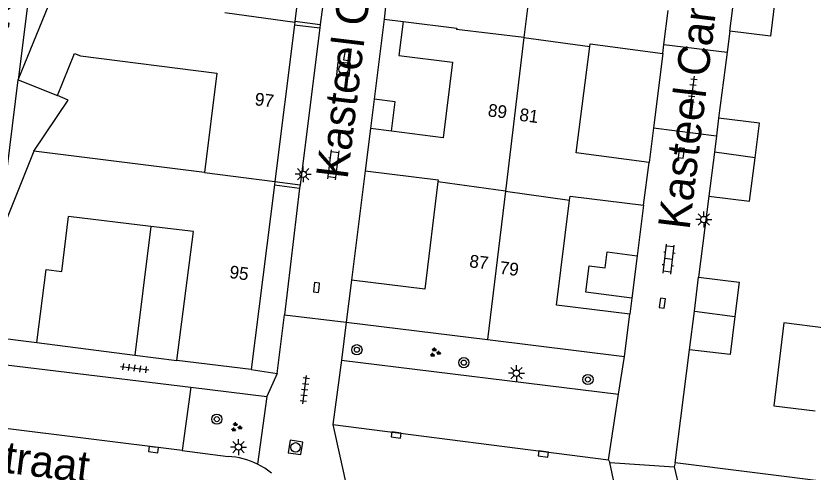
# Model space of a CAD drawing. Extents: x 131000 to 133014, y 396499 to 399001.
# Drawn here: x 131705.9 to 131768.4, y 396712.4 to 396748.2 of the extents above; entities that cross this region are included whole.
import ezdxf

# ---------------------------------------------------------------- set-up
doc = ezdxf.new("R2010")
doc.units = 0
for name, color, linetype in [('gg-afsc-erfafscheiding', 7, 'Continuous'), ('gg-afsc-muur', 7, 'Continuous'), ('gg-anno-huisnummerreeks BGT', 7, 'Continuous'), ('gg-anno-openbare ruimte label', 7, 'Continuous'), ('gg-bbg-bijgebouw', 7, 'Continuous'), ('gg-bbg-gedigitaliseerde bebouwing', 7, 'Continuous'), ('gg-bbg-gedigitaliseerde bijgebouw', 7, 'Continuous'), ('gg-bbg-hoofdgebouw', 7, 'Continuous'), ('gg-bbg-luifel en loopbrug', 7, 'Continuous'), ('gg-bbg-tussenscheiding', 7, 'Continuous'), ('gg-knt-verharding', 7, 'Continuous'), ('gg-knt-verharding nz', 7, 'Continuous'), ('gt-grn-vlakafsluiter', 7, 'Continuous'), ('gt-grn-weggrens', 7, 'Continuous'), ('gt-symb-boom', 7, 'Continuous'), ('gt-symb-groenvak', 7, 'Continuous'), ('gt-symb-klinker verharding', 7, 'Continuous'), ('gt-symb-kolk', 7, 'Continuous'), ('gt-symb-lichtmast', 7, 'Continuous'), ('gt-symb-rioolschacht', 7, 'Continuous'), ('gt-symb-tegel verharding', 7, 'Continuous')]:
    doc.layers.add(name, color=color, linetype=linetype)

# ---------------------------------------------------------------- blocks, each defined once
blk = doc.blocks.new('gt0-BOOM')
at = {"layer": 'gt-symb-boom'}
for radius in [0.4, 0.2]:
    blk.add_circle((0, 0), radius, dxfattribs=at)
blk = doc.blocks.new('gt0-KOLK')
at = {"layer": 'gt-symb-kolk'}
blk.add_lwpolyline([(0, 0), (0.375, 0), (0.375, 0.4), (-0.375, 0.4), (-0.375, 0), (0, 0)], dxfattribs=at)
blk = doc.blocks.new('gt0-LMAST')
at = {"layer": 'gt-symb-lichtmast'}
for p, q in [((-0.182, 0.173), (-0.447, 0.438)), ((-0.005, 0.246), (-0.005, 0.621)), ((0.172, 0.173), (0.437, 0.438)), ((-0.255, -0.004), (-0.63, -0.004)), ((-0.182, -0.181), (-0.447, -0.446)), ((-0.005, -0.254), (-0.005, -0.629)), ((0.437, -0.446), (0.172, -0.181)), ((0.245, -0.004), (0.62, -0.004))]:
    blk.add_line(p, q, dxfattribs=at)
blk.add_circle((-0.005, -0.004), 0.25, dxfattribs=at)
blk = doc.blocks.new('gt0-GRVAK')
at = {"layer": 'gt-symb-groenvak'}
for p, q in [((-0.11, 0.189), (-0.228, 0.24)), ((-0.182, 0.153), (0.088, 0.153)), ((-0.091, 0.211), (-0.156, 0.322)), ((-0.047, 0.214), (-0.047, 0.393)), ((-0.004, 0.211), (0.061, 0.322)), ((0.015, 0.189), (0.133, 0.24)), ((0.262, -0.052), (0.197, 0.059)), ((0.305, -0.049), (0.305, 0.13)), ((0.349, -0.052), (0.414, 0.059)), ((-0.245, -0.228), (-0.363, -0.177)), ((-0.318, -0.264), (-0.047, -0.264)), ((-0.226, -0.206), (-0.291, -0.095)), ((-0.183, -0.203), (-0.183, -0.024)), ((-0.139, -0.206), (-0.074, -0.095)), ((-0.12, -0.228), (-0.002, -0.177)), ((0.243, -0.074), (0.125, -0.023)), ((0.17, -0.11), (0.441, -0.11)), ((0.368, -0.074), (0.486, -0.023))]:
    blk.add_line(p, q, dxfattribs=at)
blk = doc.blocks.new('gt0-RS')
at = {"layer": 'gt-symb-rioolschacht'}
blk.add_lwpolyline([(-0.5, -0.5), (0.5, -0.5), (0.5, 0.5), (-0.5, 0.5)], close=True, dxfattribs=at)
blk.add_circle((0, 0), 0.375, dxfattribs=at)
blk = doc.blocks.new('gt0-TEG1')
at = {"layer": 'gt-symb-tegel verharding'}
for p, q in [((-1.125, 0), (1.125, 0)), ((-0.9, -0.25), (-0.9, 0.25)), ((-0.45, -0.25), (-0.45, 0.25)), ((0, -0.25), (0, 0.25)), ((0.45, -0.25), (0.45, 0.25)), ((0.9, -0.25), (0.9, 0.25))]:
    blk.add_line(p, q, dxfattribs=at)
blk = doc.blocks.new('gt0-KL1')
at = {"layer": 'gt-symb-klinker verharding'}
for p, q in [((-1.15, 0.3), (1.15, 0.3)), ((-1, -0.3), (-1, 0.3)), ((-0.5, 0.3), (-0.5, 0.45)), ((0, -0.3), (0, 0.3)), ((0.5, 0.3), (0.5, 0.45)), ((1, -0.3), (1, 0.3)), ((-1.15, -0.3), (1.15, -0.3)), ((-0.5, -0.45), (-0.5, -0.3)), ((0.5, -0.45), (0.5, -0.3))]:
    blk.add_line(p, q, dxfattribs=at)

msp = doc.modelspace()

# ---------------------------------------------------------------- linework, layer by layer
at = {"layer": 'gg-afsc-erfafscheiding'}
for p, q in [((131734.78, 396747.94), (131733.999, 396741.681)), ((131761.9, 396747.01), (131761.688, 396745.348)), ((131756.65, 396745.26), (131755.913, 396739.423)), ((131761.688, 396745.348), (131761.537, 396744.163)), ((131755.913, 396739.423), (131755.57, 396736.7)), ((131755.13, 396733.36), (131754.629, 396729.381)), ((131754.21, 396726.062), (131754.05, 396724.79)), ((131757.62, 396713.13), (131758.74, 396722)), ((131779.39, 396710.379), (131757.62, 396713.13))]:
    msp.add_line(p, q, dxfattribs=at)
at = {"layer": 'gg-afsc-muur'}
for p, q in [((131727.792, 396747.788), (131729.778, 396747.541)), ((131727.757, 396747.51), (131729.743, 396747.263)), ((131729.778, 396747.541), (131729.743, 396747.263)), ((131761.537, 396744.163), (131761.03, 396740.19)), ((131733.3, 396736.05), (131732.22, 396727.47)), ((131726.207, 396735.197), (131728.192, 396734.95)), ((131726.175, 396734.94), (131728.16, 396734.693)), ((131728.192, 396734.95), (131728.16, 396734.693)), ((131760.26, 396734.06), (131759.46, 396727.7)), ((131707.546, 396722.579), (131715.228, 396721.58))]:
    msp.add_line(p, q, dxfattribs=at)
at = {"layer": 'gg-bbg-bijgebouw'}
for p, q in [((131761.9, 396747.01), (131762.29, 396750.09)), ((131761.03, 396740.19), (131760.855, 396738.8)), ((131760.855, 396738.8), (131760.692, 396737.499)), ((131760.692, 396737.499), (131760.26, 396734.06)), ((131759.124, 396725.041), (131759.46, 396727.7)), ((131758.74, 396722), (131759.124, 396725.041))]:
    msp.add_line(p, q, dxfattribs=at)
for points in [[(131765.47, 396749.653), (131765.09, 396746.61), (131761.9, 396747.01)], [(131763.884, 396737.068), (131764.23, 396739.79), (131761.03, 396740.19)], [(131760.26, 396734.06), (131763.45, 396733.66), (131763.884, 396737.068)], [(131759.46, 396727.7), (131762.64, 396727.3), (131762.304, 396724.615)], [(131762.304, 396724.615), (131761.93, 396721.62), (131758.74, 396722)]]:
    msp.add_lwpolyline(points, dxfattribs=at)
at = {"layer": 'gg-bbg-gedigitaliseerde bebouwing'}
msp.add_lwpolyline([(131707.546, 396722.579), (131708.262, 396728.299), (131709.494, 396728.147), (131710.027, 396732.464)], dxfattribs=at)
at = {"layer": 'gg-bbg-gedigitaliseerde bijgebouw'}
msp.add_line((131754.629, 396729.381), (131754.21, 396726.062), dxfattribs=at)
msp.add_lwpolyline([(131754.21, 396726.062), (131750.605, 396726.522), (131750.869, 396728.589), (131752.121, 396728.429), (131752.28, 396729.681), (131754.629, 396729.381)], dxfattribs=at)
at = {"layer": 'gg-bbg-hoofdgebouw'}
for p, q in [((131729.338, 396760.071), (131727.792, 396747.788)), ((131735.14, 396751.25), (131734.78, 396747.94)), ((131706.07, 396743.18), (131708.93, 396750.16)), ((131756.737, 396745.972), (131757.06, 396748.62)), ((131727.784, 396747.725), (131727.757, 396747.51)), ((131727.792, 396747.788), (131727.784, 396747.725)), ((131734.78, 396747.94), (131736.274, 396747.759)), ((131727.757, 396747.51), (131726.207, 396735.197)), ((131756.65, 396745.26), (131756.737, 396745.972)), ((131706.07, 396743.18), (131709.15, 396741.95)), ((131733.71, 396739.37), (131733.3, 396736.05)), ((131735.358, 396739.16), (131733.71, 396739.37)), ((131707.31, 396737.59), (131704.5, 396730.66)), ((131720.7, 396735.91), (131707.31, 396737.59)), ((131755.13, 396733.36), (131755.57, 396736.7)), ((131726.207, 396735.197), (131726.175, 396734.94)), ((131726.175, 396734.94), (131724.35, 396720.44)), ((131716.475, 396731.685), (131710.027, 396732.464)), ((131732.22, 396727.47), (131731.82, 396724.16)), ((131753.64, 396721.48), (131754.05, 396724.79)), ((131731.82, 396724.16), (131742.892, 396722.8)), ((131742.892, 396722.8), (131753.64, 396721.48)), ((131724.35, 396720.44), (131718.53, 396721.15))]:
    msp.add_line(p, q, dxfattribs=at)
for points in [[(131736.274, 396747.759), (131735.938, 396745.094), (131740.157, 396744.578)], [(131755.57, 396736.7), (131749.84, 396737.45), (131750.932, 396745.809)], [(131750.932, 396745.809), (131750.96, 396746.02), (131756.65, 396745.26)], [(131709.15, 396741.95), (131710.5, 396745.26), (131710.96, 396745.08), (131721.66, 396743.72), (131720.7, 396735.91)], [(131740.157, 396744.578), (131739.43, 396738.64), (131735.358, 396739.16)], [(131733.3, 396736.05), (131739.02, 396735.34), (131739, 396735.174)], [(131739, 396735.174), (131737.97, 396726.76), (131732.22, 396727.47)], [(131749.339, 396733.745), (131749.38, 396734.07), (131755.13, 396733.36)], [(131754.05, 396724.79), (131748.31, 396725.49), (131749.339, 396733.745)], [(131718.53, 396721.15), (131719.83, 396731.28), (131716.475, 396731.685)], [(131704.127, 396727.596), (131703.577, 396723.076), (131707.546, 396722.579)], [(131769.423, 396723.698), (131766.15, 396724.103), (131765.347, 396717.612), (131768.6, 396717.21)]]:
    msp.add_lwpolyline(points, dxfattribs=at)
at = {"layer": 'gg-bbg-luifel en loopbrug'}
for p, q in [((131733.999, 396741.681), (131733.71, 396739.37)), ((131716.475, 396731.685), (131715.228, 396721.58)), ((131715.228, 396721.58), (131718.53, 396721.15))]:
    msp.add_line(p, q, dxfattribs=at)
msp.add_lwpolyline([(131735.358, 396739.16), (131735.653, 396741.47), (131733.999, 396741.681)], dxfattribs=at)
at = {"layer": 'gg-bbg-tussenscheiding'}
for p, q in [((131747.193, 396758.422), (131745.756, 396746.524)), ((131722.28, 396748.47), (131727.784, 396747.725)), ((131745.756, 396746.524), (131740.472, 396747.152)), ((131745.756, 396746.524), (131744.298, 396734.444)), ((131745.756, 396746.524), (131750.932, 396745.809)), ((131763.884, 396737.068), (131760.692, 396737.499)), ((131720.7, 396735.91), (131726.207, 396735.197)), ((131744.298, 396734.444), (131739, 396735.174)), ((131744.298, 396734.444), (131742.892, 396722.8)), ((131744.298, 396734.444), (131749.339, 396733.745)), ((131759.124, 396725.041), (131762.304, 396724.615))]:
    msp.add_line(p, q, dxfattribs=at)
msp.add_lwpolyline([(131736.274, 396747.759), (131740.483, 396747.249), (131740.472, 396747.152)], dxfattribs=at)
at = {"layer": 'gg-knt-verharding'}
for p, q in [((131731.325, 396759.825), (131729.778, 396747.541)), ((131707.65, 396755.75), (131706.07, 396743.18)), ((131729.743, 396747.263), (131728.192, 396734.95)), ((131756.737, 396745.972), (131761.688, 396745.348)), ((131704.5, 396730.66), (131706.07, 396743.18)), ((131755.913, 396739.423), (131760.855, 396738.8)), ((131728.16, 396734.693), (131726.975, 396724.755)), ((131726.4, 396720.13), (131726.975, 396724.755)), ((131726.975, 396724.755), (131731.82, 396724.16)), ((131731.82, 396724.16), (131731.43, 396721.185)), ((131753.183, 396718.513), (131753.64, 396721.48)), ((131731.43, 396721.185), (131730.77, 396716.14)), ((131731.43, 396721.185), (131753.183, 396718.513)), ((131724.35, 396720.44), (131726.4, 396720.13)), ((131719.623, 396719.063), (131718.94, 396714.083)), ((131719.623, 396719.063), (131725.58, 396718.34)), ((131725.58, 396718.34), (131724.85, 396713.02)), ((131730.77, 396716.14), (131732.4, 396708.8)), ((131718.94, 396714.083), (131722.55, 396713.63)), ((131754.035, 396706.088), (131752.488, 396713.154)), ((131752.488, 396713.154), (131757.55, 396712.813)), ((131757.55, 396712.813), (131759.23, 396705.62))]:
    msp.add_line(p, q, dxfattribs=at)
for points in [[(131703.64, 396716.004), (131704.24, 396720.93), (131719.623, 396719.063)], [(131725.96, 396712.31), (131725.425, 396712.696), (131724.85, 396713.02)]]:
    msp.add_lwpolyline(points, dxfattribs=at)
msp.add_arc((131722.216, 396707.731), 5.908, 63.52841, 86.76386, dxfattribs=at)
at = {"layer": 'gg-knt-verharding nz'}
for p, q in [((131752.39, 396713.36), (131753.183, 396718.513)), ((131718.94, 396714.083), (131703.64, 396716.004)), ((131730.77, 396716.14), (131752.39, 396713.36))]:
    msp.add_line(p, q, dxfattribs=at)
at = {"layer": 'gt-grn-vlakafsluiter'}
msp.add_lwpolyline([(131707.31, 396737.59), (131710.011, 396741.598), (131709.15, 396741.95)], dxfattribs=at)
at = {"layer": 'gt-grn-weggrens'}
for p, q in [((131726.4, 396720.13), (131725.58, 396718.34)), ((131752.39, 396713.36), (131752.488, 396713.154)), ((131757.62, 396713.13), (131757.55, 396712.813))]:
    msp.add_line(p, q, dxfattribs=at)

# ---------------------------------------------------------------- block references
at = {"layer": 'gt-symb-boom'}
for p in [(131732.652, 396722.003), (131741.036, 396720.989), (131750.778, 396719.665), (131721.663, 396716.551)]:
    msp.add_blockref('gt0-BOOM', p, dxfattribs=at)
at = {"layer": 'gt-symb-groenvak'}
for p in [(131738.776, 396721.788), (131723.18, 396715.927)]:
    msp.add_blockref('gt0-GRVAK', p, dxfattribs=at)
at = {"layer": 'gt-symb-klinker verharding'}
for p, rotation in [((131730.821, 396736.517), 82.81812146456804), ((131757.108, 396729.116), 82.99574075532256)]:
    msp.add_blockref('gt0-KL1', p, dxfattribs=dict(at, rotation=rotation))
at = {"layer": 'gt-symb-kolk'}
for p, rotation in [((131732.06, 396745.065), 81.78079075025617), ((131757.907, 396737.474), -97.75742578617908), ((131729.679, 396726.863), 82.9318599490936), ((131756.42, 396725.685), -97.75742578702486), ((131735.761, 396715.506), 172.7612734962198), ((131716.72, 396714.361), 173.10945168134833), ((131747.302, 396714.015), 172.590815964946)]:
    msp.add_blockref('gt0-KOLK', p, dxfattribs=dict(at, rotation=rotation))
at = {"layer": 'gt-symb-lichtmast'}
for p in [(131728.441, 396735.779), (131759.872, 396732.223), (131745.166, 396720.163), (131723.362, 396714.369)]:
    msp.add_blockref('gt0-LMAST', p, dxfattribs=at)
at = {"layer": 'gt-symb-rioolschacht'}
for p, rotation in [((131731.605, 396744.019), 83.91299166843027), ((131727.837, 396714.334), 81.65913313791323)]:
    msp.add_blockref('gt0-RS', p, dxfattribs=dict(at, rotation=rotation))
at = {"layer": 'gt-symb-tegel verharding'}
for p, rotation in [((131758.972, 396742.356), -97.23872650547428), ((131715.219, 396720.557), -7.295560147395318), ((131728.563, 396718.86), 82.53402593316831)]:
    msp.add_blockref('gt0-TEG1', p, dxfattribs=dict(at, rotation=rotation))

# ---------------------------------------------------------------- texts
at = {"layer": 'gg-anno-huisnummerreeks BGT'}
for s, rotation, p in [('97', 353, (131724.598, 396741.202)), ('89', 353, (131742.884, 396740.33)), ('81', 352.5, (131745.354, 396739.984)), ('87', 353, (131741.428, 396728.484)), ('79', 352.9, (131743.805, 396727.97)), ('95', 352.7, (131722.612, 396727.633))]:
    msp.add_text(s, height=1, rotation=rotation, dxfattribs=at).set_placement(p)
at = {"layer": 'gg-anno-openbare ruimte label'}
for s, rotation, p in [('Slot Loevesteinstraat', 82.1, (131703.588, 396734.504)), ('Kasteel Cannestraat', 83.1, (131731.916, 396735.34)), ('Kasteel Cannestraat', 83.1, (131758.741, 396731.364)), ('Slot Loevesteinstraat', 352.8, (131680.53, 396715.456))]:
    msp.add_text(s, height=2.5, rotation=rotation, dxfattribs=at).set_placement(p)

doc.saveas('drawing.dxf')
